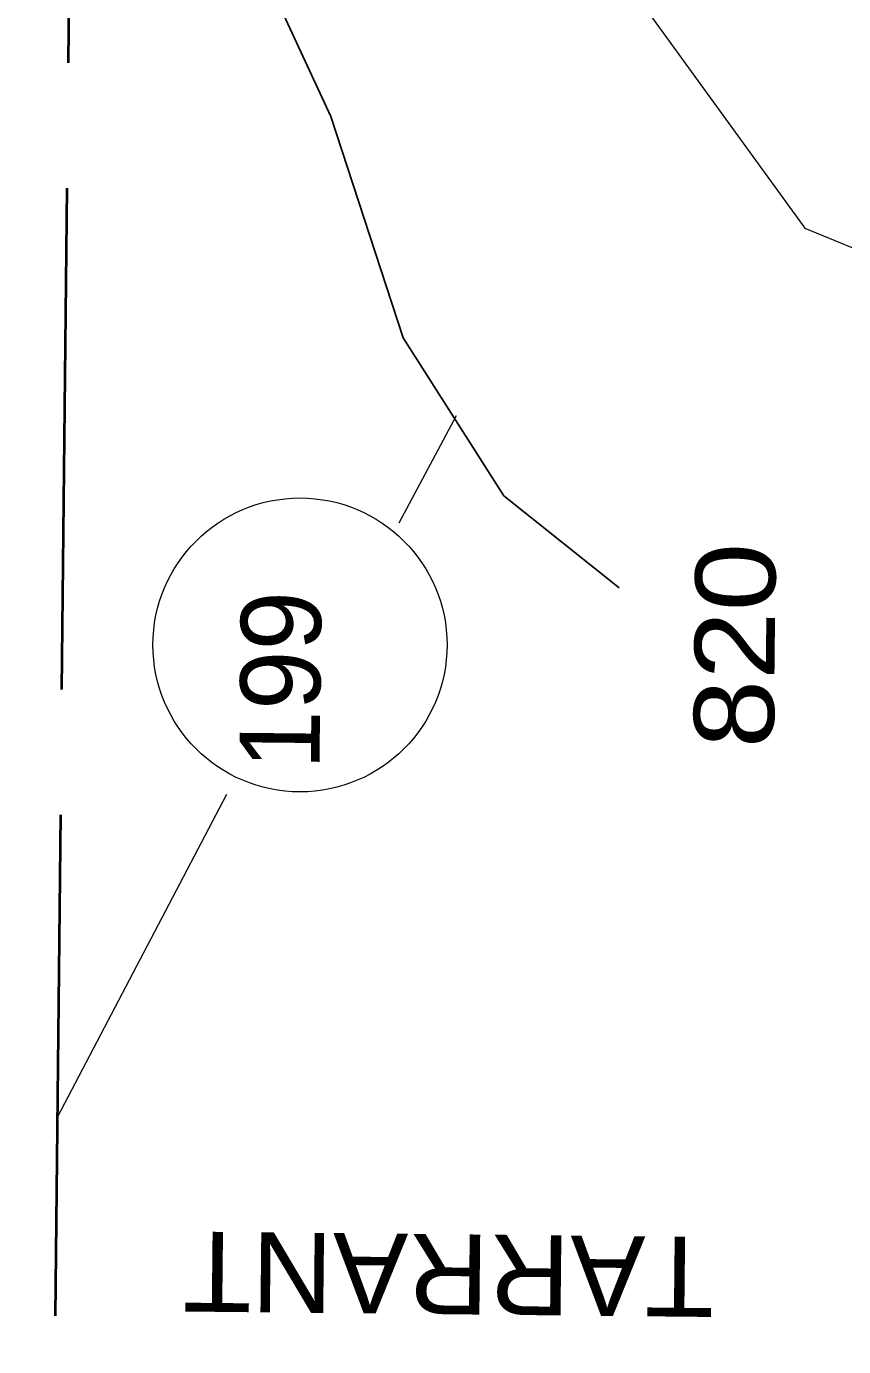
# Model space of a CAD drawing. Extents: x 2356576 to 2377878, y 6966390 to 6990634.
# Drawn here: x 2365851.2 to 2365920.6, y 6968773.4 to 6968885.6 of the extents above; entities that cross this region are included whole.
import ezdxf

# ---------------------------------------------------------------- set-up
doc = ezdxf.new("R2010")
doc.units = 0
doc.header["$LTSCALE"] = 7.1
doc.linetypes.add('LONG_DASHED', pattern=[7.5, 6, -1.5])
doc.layers.add('19', color=7, linetype='Continuous', lineweight=13)
doc.layers.add('8', color=7, linetype='Continuous', lineweight=13)

msp = doc.modelspace()

# ---------------------------------------------------------------- linework, layer by layer
at = {"layer": '19'}
for p, q in [((2365882.854, 6968843.407), (2365887.721, 6968852.538)), ((2365853.858, 6968792.909), (2365868.243, 6968820.366))]:
    msp.add_line(p, q, dxfattribs=at)
at = {"layer": '19', "lineweight": 25}
msp.add_line((2365891.759, 6968845.715), (2365901.55, 6968837.902), dxfattribs=at)
msp.add_lwpolyline([(2365891.759, 6968845.715), (2365883.197, 6968859.125), (2365877.06, 6968877.937), (2365870.87, 6968891.326), (2365864.889, 6968904.737), (2365858.697, 6968920.974), (2365855.04, 6968930.224), (2365855.178, 6968943.544), (2365855.399, 6968964.81), (2365856.978, 6968980.999), (2365860.808, 6968988.88), (2365864.807, 6968992.646)], dxfattribs=at)
at = {"layer": '19', "linetype": 'LONG_DASHED', "lineweight": 40}
msp.add_lwpolyline([(2365767.5, 6968670.405), (2365852.579, 6968669.524), (2365854.981, 6968901.299), (2365769.901, 6968902.181), (2365767.496, 6968669.985)], dxfattribs=at)
at = {"layer": '19'}
msp.add_lwpolyline([(2365898.594, 6968894.279), (2365917.316, 6968868.46), (2365940.231, 6968859.014)], dxfattribs=at)
msp.add_circle((2365874.445, 6968833.039), 12.486, dxfattribs=at)
at = {"layer": '8'}
for p, q in [((2365882.854, 6968843.407), (2365887.721, 6968852.538)), ((2365853.858, 6968792.909), (2365868.243, 6968820.366))]:
    msp.add_line(p, q, dxfattribs=at)
at = {"layer": '8', "lineweight": 25}
msp.add_line((2365891.759, 6968845.715), (2365901.55, 6968837.902), dxfattribs=at)
msp.add_lwpolyline([(2365891.759, 6968845.715), (2365883.197, 6968859.125), (2365877.06, 6968877.937), (2365870.87, 6968891.326), (2365864.889, 6968904.737), (2365858.697, 6968920.974), (2365855.04, 6968930.224), (2365855.178, 6968943.544), (2365855.399, 6968964.81), (2365856.978, 6968980.999), (2365860.808, 6968988.88), (2365864.807, 6968992.646)], dxfattribs=at)
at = {"layer": '8', "linetype": 'LONG_DASHED', "lineweight": 40}
msp.add_lwpolyline([(2365767.5, 6968670.405), (2365852.579, 6968669.524), (2365854.981, 6968901.299), (2365769.901, 6968902.181), (2365767.496, 6968669.985)], dxfattribs=at)
at = {"layer": '8'}
msp.add_lwpolyline([(2365898.594, 6968894.279), (2365917.316, 6968868.46), (2365940.231, 6968859.014)], dxfattribs=at)
msp.add_circle((2365874.445, 6968833.039), 12.486, dxfattribs=at)

# ---------------------------------------------------------------- texts
at = {"layer": '19'}
for s, rotation, width, p in [('820', 89.406, 1.15, (2365914.669, 6968824.233)), ('TARRANT', 179.406, 1.05, (2365909.619, 6968782.731))]:
    msp.add_text(s, height=6.798, rotation=rotation, dxfattribs=dict(at, width=width)).set_placement(p)
msp.add_text('199', height=6.798, rotation=89.406, dxfattribs=at).set_placement((2365876.097, 6968822.412))
at = {"layer": '8'}
for s, rotation, width, p in [('820', 89.406, 1.15, (2365914.669, 6968824.233)), ('TARRANT', 179.406, 1.05, (2365909.619, 6968782.731))]:
    msp.add_text(s, height=6.798, rotation=rotation, dxfattribs=dict(at, width=width)).set_placement(p)
msp.add_text('199', height=6.798, rotation=89.406, dxfattribs=at).set_placement((2365876.097, 6968822.412))

doc.saveas('drawing.dxf')
